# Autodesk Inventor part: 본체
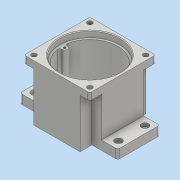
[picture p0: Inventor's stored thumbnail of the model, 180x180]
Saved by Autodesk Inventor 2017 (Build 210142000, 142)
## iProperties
Part Number: 본체
Material: 일반
Document SubType Name: Modeling
Designer: user
Density: 1 g/cm^3
Appearance: 기본값
Author: user
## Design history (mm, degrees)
sketch "스케치1"
  geometry: L1 (0, 30)-(140, 30); L2 (140, 30)-(140, -30); L3 (140, -30)-(0, -30); L4 (0, -30)-(0, 30); L5 (37, 47)-(103, 47); L6 (103, 47)-(103, -47); L7 (103, -47)-(37, -47); L8 (37, -47)-(37, 47); 6 further points
  constraints: 16 end point, 5 midpoint, 4 parallel, 2 coincident, 2 horizontal, 2 horizontal alignment, 2 perpendicular, 1 vertical alignment
  dimensions: "d0" = 140 distance between parallel lines of L2 L4; "d1" = 60 distance between parallel lines of L3 L1; "d2" = 66 distance between parallel lines of L8 L6; "d3" = 94 distance between parallel lines of L7 L5
extrude "돌출1" new body sketch "스케치1" distance "d4" = 13; taper "d5" = 0 deg
sketch "스케치2"
  geometry: L1 (37, 47)-(103, 47); L2 (103, 47)-(103, -47); L3 (103, -47)-(37, -47); L4 (37, -47)-(37, 47); L5 (103, 47)-(37, 47) reference; L6 (103, 30)-(103, 47) reference; L7 (23, 30)-(117, 30); L8 (117, 30)-(117, -30); L9 (117, -30)-(23, -30); L10 (23, -30)-(23, 30); L11 (140, 30)-(103, 30) reference; L12 (103, -30)-(140, -30) reference; 1 further point
  constraints: 16 end point, 4 collinear, 4 parallel, 2 horizontal, 2 perpendicular
  dimensions: "d6" = 66 distance between parallel lines of L2 L4; "d7" = 94 distance between parallel lines of L3 L1; "d8" = 94 distance of L7.start L7.end; "d10" = 14 distance between parallel lines of L4 L10
extrude "돌출2" join sketch "스케치2" distance "d11" = 57; taper "d12" = 0 deg
sketch "스케치3"
  geometry: L1 (23, 47)-(117, 47); L2 (117, 47)-(117, -47); L3 (117, -47)-(23, -47); L4 (23, -47)-(23, 47); L5 (103, 47)-(37, 47) reference; L6 (117, -30)-(117, 30) reference; L7 (37, -47)-(103, -47) reference; L8 (23, 30)-(23, -30) reference; 1 further point
  constraints: 8 end point, 4 collinear, 2 parallel, 1 horizontal, 1 perpendicular
extrude "돌출3" join sketch "스케치3" distance "d13" = 10; taper "d14" = 0 deg
sketch "스케치4"
  geometry: C1 r 43 at (70, 0); 1 further point
  constraints: 1 centre point, 1 horizontal alignment
  dimensions: "d15" = 70 distance of C1.centre point (0, 0); "d16" = 86 diameter of C1
extrude "돌출4" cut sketch "스케치4" distance "d17" = 9; taper "d18" = 0 deg
sketch "스케치5"
  geometry: L1 (-70, 30)-(-70, -30) reference; C1 r 40 at (0, 0); 2 further points
  constraints: 1 centre point, 1 horizontal alignment, 1 midpoint
  dimensions: "d19" = 80 diameter of C1; "d20" = 70 distance of point (-70, 0) C1.centre
extrude "돌출5" cut sketch "스케치5" distance "d21" = 62; taper "d22" = 0 deg
sketch "스케치11"
  geometry: L1 (0, 0)-(-140, 0); L2 (-117, 47)-(-23, 47) reference; L3 (-70, 47)-(-70, 0); L4 (-70, 0)-(-70, 11); L5 (0, -30)-(0, 30) reference; C1 r 27.5 at (-70, 11)
  constraints: 6 end point, 2 midpoint, 1 centre point, 1 coincident, 1 horizontal, 1 point on line
  dimensions: "d33" = 11 distance of L3.end L4.end; "d34" = 55 diameter of C1; "d35" = 70 distance from line of L4.end L5
extrude "돌출8" join sketch "스케치11" distance "d36" = 7; taper "d37" = 0 deg
sketch "스케치12"
  geometry: L1 (70, -41)-(70, 19) reference; C1 r 16 at (0, 0); C2 r 27.5 at (0, 0) reference; 1 further point
  constraints: 1 centre point, 1 concentric
  dimensions: "d38" = 32 diameter of C1
extrude "돌출9" cut sketch "스케치12" distance "d40" = 8.3; taper "d41" = 0 deg
sketch "스케치13"
  geometry: L1 (70, -41)-(70, 19) reference; C1 r 12.5 at (0, 0); C2 r 16 at (0, 0) reference; 1 further point
  constraints: 1 centre point, 1 concentric
  dimensions: "d44" = 25 diameter of C1
extrude "돌출10" cut sketch "스케치13" distance "d45" = 4.7; taper "d46" = 0 deg
sketch "스케치16"
  geometry: C1 r 17.5 at (0, 0); C2 r 16 at (0, 0) reference; 1 further point
  constraints: 1 centre point, 1 concentric
  dimensions: "d47" = 35 diameter of C1
extrude "돌출11" cut sketch "스케치16" distance "d48" = 10; taper "d49" = 0 deg
sketch "스케치19"
  geometry: C1 r 21 at (0, 11); C2 r 15 at (0, -20); C3 r 12.5 at (0, 11) reference; 1 further point
  constraints: 2 centre point, 1 coincident, 1 vertical alignment
  dimensions: "d53" = 42 diameter of C1; "d54" = 30 diameter of C2; "d55" = 31 distance of C2.centre C1.centre
extrude "돌출12" join sketch "스케치19" distance "d56" = 7; taper "d57" = 0 deg
hole "구멍1" diameter "d60" = 35; stored, may be unused: countersink angle "d64" = 90 deg, drill point angle "d66" = 0 deg; dims "d61" = 6, "d62" = 4, "d63" = 2, "d65" = 10, "d67" = 10, "d68" = 10
sketch "스케치23"
  geometry: L1 (47, 47)-(-47, 47) reference; L2 (70, -30)-(70, 30) reference; C1 r 11 at (0, -20); A1 r 15 centre (0, -20) between (-8.978, -7.984) and (8.978, -7.984) reference; 1 further point
  constraints: 1 centre point, 1 concentric
  dimensions: "d72" = 22 diameter of C1
extrude "돌출13" cut sketch "스케치23" distance "d73" = 7; taper "d74" = 0 deg
sketch "스케치24"
  geometry: C1 r 9.5 at (0, 0); C2 r 11 at (0, 0) reference; 1 further point
  constraints: 1 centre point, 1 concentric
  dimensions: "d75" = 19 diameter of C1
extrude "돌출14" cut sketch "스케치24" distance "d76" = 3; taper "d77" = 0 deg
fillet "모깎기1" dims "d78" = 3
sketch "스케치25"
  geometry: L1 (0, 30)-(-37, 30) reference; L2 (-37, -30)-(0, -30) reference; L3 (0, -30)-(0, 30) reference; L4 (-103, 30)-(-140, 30) reference; L5 (-140, -30)-(-103, -30) reference; C1 r 2.25 at (-10, 19); C2 r 2.25 at (-10, -19); C3 r 2.25 at (-130, 19); C4 r 2.25 at (-130, -19); 1 further point
  constraints: 4 centre point
  dimensions: "d79" = 4.5 diameter of C1; "d81" = 4.5 diameter of C2; "d82" = 38 distance of C2.centre C1.centre; "d83" = 11 distance from line of C1.centre L1; "d84" = 11 distance from line of C2.centre L2; "d85" = 4.5 diameter of C3; "d86" = 4.5 diameter of C4; "d87" = 38 distance of C4.centre C3.centre; "d88" = 120 distance of C1.centre C3.centre; "d89" = 10 distance from line of L3 C1.centre; "d90" = 11 distance from line of L4 C3.centre; "d91" = 11 distance from line of L5 C4.centre
extrude "돌출15" cut sketch "스케치25" distance "d92" = 8; taper "d93" = 0 deg
sketch "스케치26"
  geometry: L1 (10, 11)-(10, -49) reference; L2 (-13, 11)-(10, 11) reference; C1 r 5 at (0, 0); 1 further point
  constraints: 1 centre point
  dimensions: "d94" = 10 diameter of C1; "d95" = 10 distance from line of L1 C1.centre; "d96" = 11 distance from line of C1.centre L2
extrude "돌출16" cut sketch "스케치26" distance "d97" = 5; taper "d98" = 0 deg
sketch "스케치28"
  geometry: L1 (-23, 30)-(-23, 47) reference; L2 (-117, 47)-(-117, 30) reference; L3 (-23, 47)-(-37, 47) reference; C1 r 3.5 at (-30, 40); C2 r 3.5 at (-110, 40); 1 further point
  constraints: 2 centre point
  dimensions: "d105" = 80 distance of C2.centre C1.centre; "d106" = 7 distance from line of C1.centre L1; "d107" = 7 distance from line of L2 C2.centre; "d108" = 7 diameter of C2; "d109" = 7 diameter of C1; "d111" = 40 vertical distance of point (0, 0) C1.centre
extrude "돌출17" cut sketch "스케치28" stored distance "d112" = 100; taper "d113" = 0 deg
sketch "스케치29"
  geometry: L1 (35.778, 3.994)-(39.8, 3.994); L2 (35.778, -3.994)-(39.8, -3.994); L3 (-39.8, 3.994)-(-35.778, 3.994); L4 (-35.778, -3.994)-(-39.8, -3.994); A1 r 36 centre (0, 0) between (-36, 0) and (36, 0); A2 r 4 centre (-36, 0) between (-35.778, 3.994) and (-35.778, -3.994); A3 r 4 centre (36, 0) between (35.778, 3.994) and (35.778, -3.994); A4 r 40 centre (0, 0) between (39.8, 3.994) and (39.8, -3.994) reference; 1 further point
  constraints: 13 point on circle, 8 end point, 3 centre point, 3 horizontal, 1 parallel
  dimensions: "d114" = 72 diameter of A1; "d115" = 8 diameter of A2; "d116" = 8 diameter of A3
extrude "돌출18" join sketch "스케치29" distance "d117" = 62; taper "d118" = 0 deg
sketch "스케치30"
  geometry: C1 r 2 at (-36, 0); C2 r 2 at (36, 0); A1 r 4 centre (-36, 0) between (-35.778, -3.994) and (-35.778, 3.994) reference; A2 r 4 centre (36, 0) between (35.778, 3.994) and (35.778, -3.994) reference; 1 further point
  constraints: 2 centre point, 2 coincident
  dimensions: "d119" = 4 diameter of C1; "d120" = 4 diameter of C2
hole "구멍2" sketch "스케치30" at (36, 0), (-36, 0) diameter "d121" = 3.242; stored, may be unused: countersink angle "d125" = 90 deg, drill point angle "d127" = 118 deg; dims "d122" = 7, "d123" = 4, "d124" = 2, "d126" = 9
chamfer "모따기1" distance "d128" = 1; stored, may be unused: second distance "d129" = 2, angle "d130" = 45 deg
node "작업 평면1"
chamfer "모따기2" distance "d131" = 1; stored, may be unused: second distance "d132" = 2, angle "d133" = 45 deg
chamfer "모따기3" distance "d134" = 0.8; stored, may be unused: second distance "d135" = 2, angle "d136" = 30 deg
fillet "모깎기2" dims "d137" = 3
fillet "모깎기3" dims "d138" = 3
sketch "스케치32"
  geometry: L1 (0, 0)-(0, -70) reference; L2 (80, -80)-(-14, -80) reference; 2 further points
  constraints: 1 other
  dimensions: "d140" = 33 distance from line of L1 point (33, -40); "d144" = 40 distance from line of point (33, -40) L2
feature "엠보싱1" sketch "스케치32" dims "d142" = 0.5, "d143" = 0
fillet "모깎기5" dims "d145" = 3
fillet "모깎기6" dims "d146" = 3
node "솔리드1"
pattern_linear "직사각형 패턴1" dims "d101" = 38, "d104" = 120
mirror "미러1"
